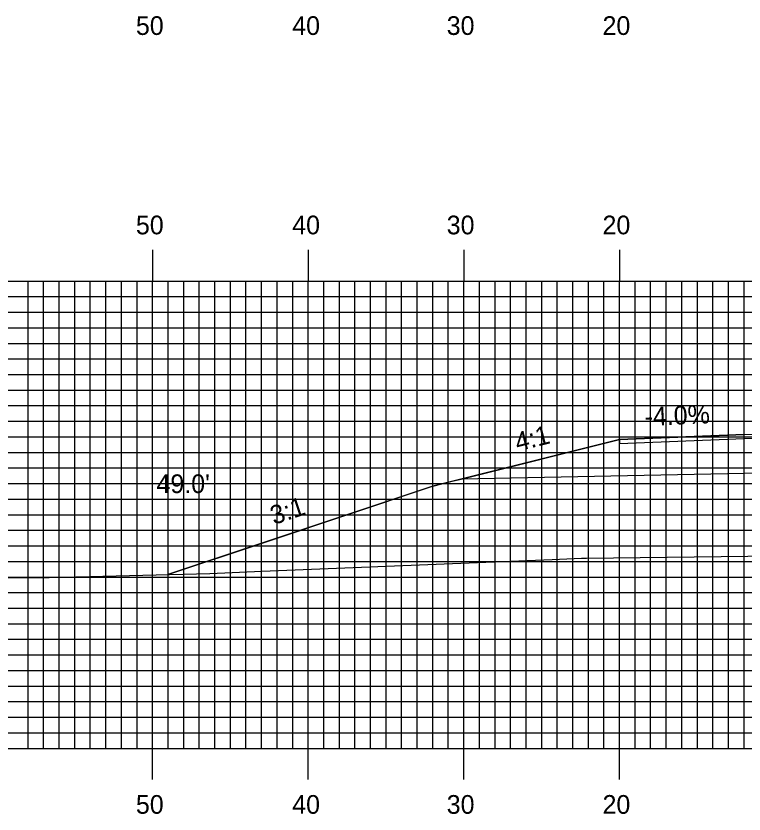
# Model space of a CAD drawing. Extents: x 1777531 to 1777875, y 442591 to 442811.
# Drawn here: x 1777638.5 to 1777685.3, y 442649.4 to 442700.7 of the extents above; entities that cross this region are included whole.
import ezdxf

# ---------------------------------------------------------------- set-up
doc = ezdxf.new("R2010")
doc.units = 0
for name, color, linetype in [('ANNOTATION', 7, 'Continuous'), ('D_Roadway_Centerline', 7, 'Continuous'), ('D_Roadway_Edge_Shoulder', 7, 'Continuous'), ('D_Roadway_SlopeLines', 7, 'Continuous'), ('D_Roadway_SubGrade', 7, 'Continuous'), ('D_Text_Standard', 7, 'Continuous'), ('H_V ANNOTATION', 7, 'Continuous'), ('MAJOR', 7, 'Continuous'), ('MINOR', 7, 'Continuous'), ('S_Roadway_Centerline', 7, 'Continuous')]:
    doc.layers.add(name, color=color, linetype=linetype)

msp = doc.modelspace()

# ---------------------------------------------------------------- linework, layer by layer
at = {"layer": 'D_Roadway_Centerline'}
msp.add_lwpolyline([(1777648.264, 442664.825), (1777648.266, 442664.826), (1777654.447, 442666.886), (1777665.203, 442670.471), (1777665.277, 442670.496), (1777665.285, 442670.498), (1777666.523, 442670.808), (1777667.103, 442670.953), (1777677.277, 442673.496), (1777685.277, 442673.816), (1777686.395, 442673.839), (1777697.277, 442674.056), (1777709.262, 442673.816), (1777709.276, 442673.816), (1777717.263, 442673.497), (1777717.277, 442673.496), (1777717.294, 442673.492), (1777727.451, 442670.953), (1777730.135, 442670.282), (1777740.516, 442667.686)], dxfattribs=at)
at = {"layer": 'D_Roadway_Edge_Shoulder'}
msp.add_lwpolyline([(1777685.277, 442673.816), (1777677.277, 442673.496), (1777677.277, 442673.246), (1777685.277, 442673.566)], close=True, dxfattribs=at)
at = {"layer": 'D_Roadway_SlopeLines'}
msp.add_lwpolyline([(1777677.277, 442673.496), (1777665.277, 442670.496), (1777648.264, 442664.825)], dxfattribs=at)
at = {"layer": 'D_Roadway_SubGrade'}
msp.add_lwpolyline([(1777685.277, 442671.316), (1777667.103, 442670.953), (1777677.277, 442673.496), (1777677.277, 442673.246), (1777685.277, 442673.566), (1777697.277, 442673.806), (1777709.276, 442673.566), (1777717.277, 442673.246), (1777717.277, 442673.496), (1777727.451, 442670.953), (1777709.276, 442671.316), (1777697.277, 442671.556)], close=True, dxfattribs=at)
at = {"layer": 'MAJOR'}
for p, q in [((1777647.277, 442685.669), (1777647.277, 442683.665)), ((1777657.277, 442685.669), (1777657.277, 442683.665)), ((1777667.277, 442685.669), (1777667.277, 442683.665)), ((1777677.277, 442685.669), (1777677.277, 442683.665)), ((1777557.277, 442683.665), (1777837.277, 442683.665)), ((1777557.277, 442683.665), (1777837.277, 442683.665)), ((1777647.277, 442653.665), (1777647.277, 442683.665)), ((1777657.277, 442653.665), (1777657.277, 442683.665)), ((1777667.277, 442653.665), (1777667.277, 442683.665)), ((1777677.277, 442653.665), (1777677.277, 442683.665)), ((1777557.277, 442678.665), (1777837.277, 442678.665)), ((1777557.277, 442673.665), (1777837.277, 442673.665)), ((1777557.277, 442668.665), (1777837.277, 442668.665)), ((1777557.277, 442663.665), (1777837.277, 442663.665)), ((1777557.277, 442658.665), (1777837.277, 442658.665)), ((1777557.277, 442653.665), (1777837.277, 442653.665)), ((1777557.277, 442653.665), (1777837.277, 442653.665)), ((1777647.277, 442651.661), (1777647.277, 442653.665)), ((1777657.277, 442651.661), (1777657.277, 442653.665)), ((1777667.277, 442651.661), (1777667.277, 442653.665)), ((1777677.277, 442651.661), (1777677.277, 442653.665))]:
    msp.add_line(p, q, dxfattribs=at)
at = {"layer": 'MINOR'}
for p, q in [((1777639.277, 442653.665), (1777639.277, 442683.665)), ((1777640.277, 442653.665), (1777640.277, 442683.665)), ((1777641.277, 442653.665), (1777641.277, 442683.665)), ((1777642.277, 442653.665), (1777642.277, 442683.665)), ((1777643.277, 442653.665), (1777643.277, 442683.665)), ((1777644.277, 442653.665), (1777644.277, 442683.665)), ((1777645.277, 442653.665), (1777645.277, 442683.665)), ((1777646.277, 442653.665), (1777646.277, 442683.665)), ((1777648.277, 442653.665), (1777648.277, 442683.665)), ((1777649.277, 442653.665), (1777649.277, 442683.665)), ((1777650.277, 442653.665), (1777650.277, 442683.665)), ((1777651.277, 442653.665), (1777651.277, 442683.665)), ((1777652.277, 442653.665), (1777652.277, 442683.665)), ((1777653.277, 442653.665), (1777653.277, 442683.665)), ((1777654.277, 442653.665), (1777654.277, 442683.665)), ((1777655.277, 442653.665), (1777655.277, 442683.665)), ((1777656.277, 442653.665), (1777656.277, 442683.665)), ((1777658.277, 442653.665), (1777658.277, 442683.665)), ((1777659.277, 442653.665), (1777659.277, 442683.665)), ((1777660.277, 442653.665), (1777660.277, 442683.665)), ((1777661.277, 442653.665), (1777661.277, 442683.665)), ((1777662.277, 442653.665), (1777662.277, 442683.665)), ((1777663.277, 442653.665), (1777663.277, 442683.665)), ((1777664.277, 442653.665), (1777664.277, 442683.665)), ((1777665.277, 442653.665), (1777665.277, 442683.665)), ((1777666.277, 442653.665), (1777666.277, 442683.665)), ((1777668.277, 442653.665), (1777668.277, 442683.665)), ((1777669.277, 442653.665), (1777669.277, 442683.665)), ((1777670.277, 442653.665), (1777670.277, 442683.665)), ((1777671.277, 442653.665), (1777671.277, 442683.665)), ((1777672.277, 442653.665), (1777672.277, 442683.665)), ((1777673.277, 442653.665), (1777673.277, 442683.665)), ((1777674.277, 442653.665), (1777674.277, 442683.665)), ((1777675.277, 442653.665), (1777675.277, 442683.665)), ((1777676.277, 442653.665), (1777676.277, 442683.665)), ((1777678.277, 442653.665), (1777678.277, 442683.665)), ((1777679.277, 442653.665), (1777679.277, 442683.665)), ((1777680.277, 442653.665), (1777680.277, 442683.665)), ((1777681.277, 442653.665), (1777681.277, 442683.665)), ((1777682.277, 442653.665), (1777682.277, 442683.665)), ((1777683.277, 442653.665), (1777683.277, 442683.665)), ((1777684.277, 442653.665), (1777684.277, 442683.665)), ((1777685.277, 442653.665), (1777685.277, 442683.665)), ((1777557.277, 442682.665), (1777837.277, 442682.665)), ((1777557.277, 442681.665), (1777837.277, 442681.665)), ((1777557.277, 442680.665), (1777837.277, 442680.665)), ((1777557.277, 442679.665), (1777837.277, 442679.665)), ((1777557.277, 442677.665), (1777837.277, 442677.665)), ((1777557.277, 442676.665), (1777837.277, 442676.665)), ((1777557.277, 442675.665), (1777837.277, 442675.665)), ((1777557.277, 442674.665), (1777837.277, 442674.665)), ((1777557.277, 442672.665), (1777837.277, 442672.665)), ((1777557.277, 442671.665), (1777837.277, 442671.665)), ((1777557.277, 442670.665), (1777837.277, 442670.665)), ((1777557.277, 442669.665), (1777837.277, 442669.665)), ((1777557.277, 442667.665), (1777837.277, 442667.665)), ((1777557.277, 442666.665), (1777837.277, 442666.665)), ((1777557.277, 442665.665), (1777837.277, 442665.665)), ((1777557.277, 442664.665), (1777837.277, 442664.665)), ((1777557.277, 442662.665), (1777837.277, 442662.665)), ((1777557.277, 442661.665), (1777837.277, 442661.665)), ((1777557.277, 442660.665), (1777837.277, 442660.665)), ((1777557.277, 442659.665), (1777837.277, 442659.665)), ((1777557.277, 442657.665), (1777837.277, 442657.665)), ((1777557.277, 442656.665), (1777837.277, 442656.665)), ((1777557.277, 442655.665), (1777837.277, 442655.665)), ((1777557.277, 442654.665), (1777837.277, 442654.665))]:
    msp.add_line(p, q, dxfattribs=at)
at = {"layer": 'S_Roadway_Centerline'}
msp.add_lwpolyline([(1777631.326, 442664.6), (1777640.64, 442664.628), (1777650.949, 442664.895), (1777654.292, 442665.032), (1777672.947, 442665.79), (1777674.835, 442665.867), (1777675.151, 442665.875), (1777687.255, 442666.018), (1777698.469, 442666.584), (1777699.998, 442666.62), (1777710.165, 442666.853), (1777721.734, 442667.499), (1777722.341, 442667.529), (1777727.789, 442667.57), (1777743.766, 442667.717), (1777745.497, 442667.775), (1777756.941, 442668.54)], dxfattribs=at)

# ---------------------------------------------------------------- texts
at = {"layer": 'ANNOTATION'}
for s, rotation, p in [('-4.0%', 2.2905, (1777678.909, 442674.363)), ('4:1', 14.0348, (1777670.726, 442672.72)), ('3:1', 18.4345, (1777655.073, 442668.003))]:
    msp.add_text(s, height=1.2, rotation=rotation, dxfattribs=at).set_placement(p)
at = {"layer": 'D_Text_Standard'}
msp.add_text("49.0'", height=1.2, dxfattribs=at).set_placement((1777647.528, 442670.053))
at = {"layer": 'H_V ANNOTATION'}
for s, p in [('50', (1777646.206, 442699.465)), ('40', (1777656.249, 442699.465)), ('30', (1777666.174, 442699.465)), ('20', (1777676.185, 442699.465)), ('50', (1777646.206, 442686.665)), ('40', (1777656.249, 442686.665)), ('30', (1777666.174, 442686.665)), ('20', (1777676.185, 442686.665)), ('50', (1777646.206, 442649.465)), ('40', (1777656.249, 442649.465)), ('30', (1777666.174, 442649.465)), ('20', (1777676.185, 442649.465))]:
    msp.add_text(s, height=1.2, dxfattribs=at).set_placement(p)

doc.saveas('drawing.dxf')
